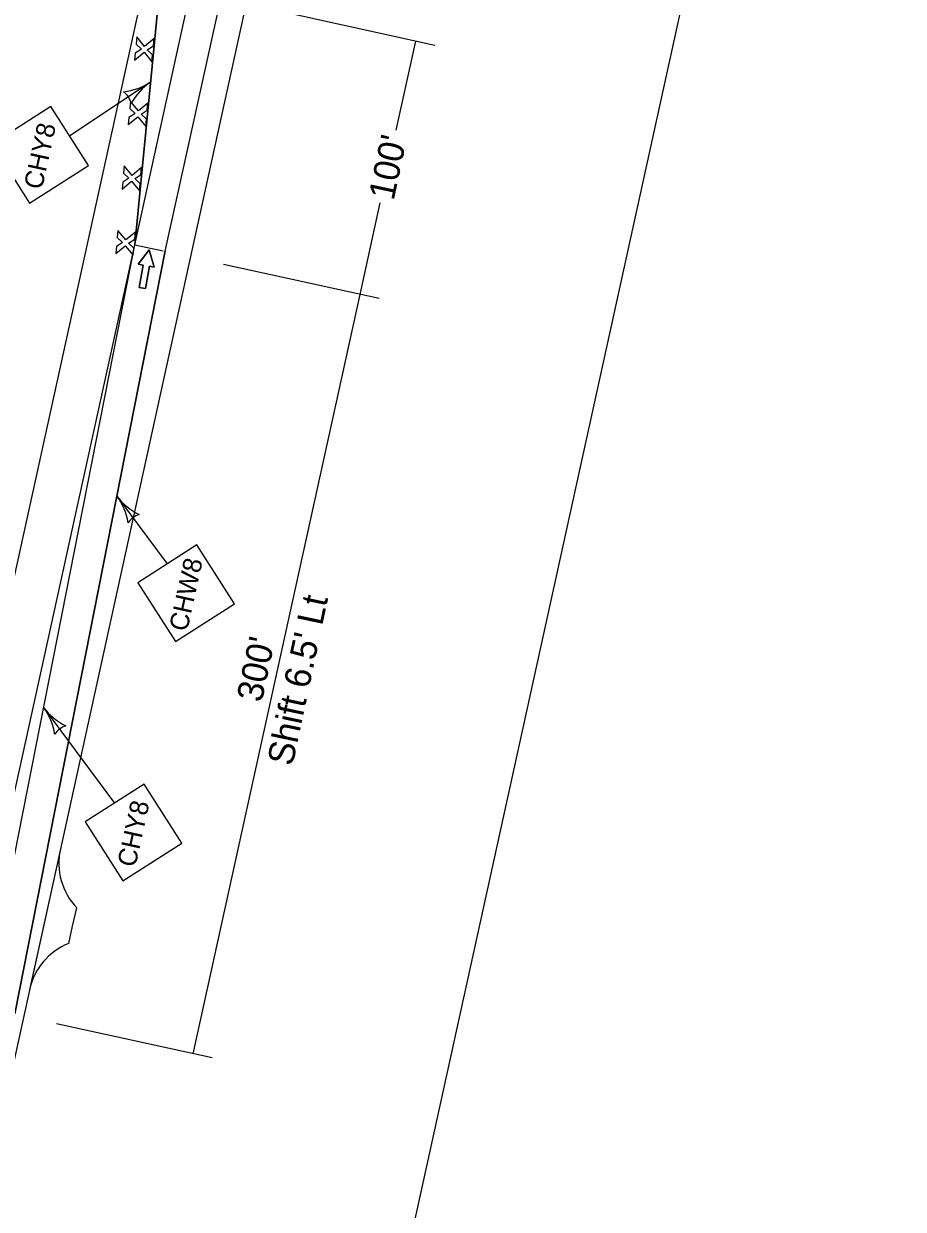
# Model space of a CAD drawing. Extents: x 14104283 to 14120882, y 8635219 to 8671666.
# Drawn here: x 14108147 to 14108486.3, y 8640438 to 8640895.4 of the extents above; entities that cross this region are included whole.
import ezdxf

# ---------------------------------------------------------------- set-up
doc = ezdxf.new("R2010")
doc.units = 0
for name, color, linetype in [('Cell', 7, 'Continuous'), ('dsnNonPlotable', 7, 'Continuous'), ('dsnPaintExistingEdgeLineRightWhite', 7, 'Continuous'), ('dsnPaintPlaceBrokenLineWhite', 7, 'Continuous'), ('dsnPaintRemoveDoubleCenterLineYellow', 7, 'Continuous'), ('dsnShadingGranular', 7, 'Continuous'), ('dsnShadingPaved', 7, 'Continuous'), ('dsnStdLabel', 7, 'Continuous'), ('dsnStgShadingPrevPav', 7, 'Continuous'), ('dsnTapePlaceChannelizingLaneWhite', 7, 'Continuous'), ('dsnTapePlaceChannelizingLaneYellow', 7, 'Continuous')]:
    doc.layers.add(name, color=color, linetype=linetype)

msp = doc.modelspace()

# ---------------------------------------------------------------- linework, layer by layer
at = {"layer": 'Cell'}
for p, q in [((14108190.6, 8640890.31), (14108190.33, 8640887.57)), ((14108190.33, 8640887.57), (14108192.4, 8640885.61)), ((14108193.63, 8640886.62), (14108190.6, 8640890.31)), ((14108197.32, 8640889.66), (14108193.63, 8640886.62)), ((14108194.64, 8640885.39), (14108197.05, 8640886.92)), ((14108197.05, 8640886.92), (14108197.32, 8640889.66)), ((14108189.73, 8640881.35), (14108193.41, 8640884.38)), ((14108189.99, 8640884.09), (14108189.73, 8640881.35)), ((14108192.4, 8640885.61), (14108189.99, 8640884.09)), ((14108193.41, 8640884.38), (14108196.45, 8640880.7)), ((14108196.71, 8640883.43), (14108194.64, 8640885.39)), ((14108196.45, 8640880.7), (14108196.71, 8640883.43)), ((14108188.18, 8640865.42), (14108187.92, 8640862.69)), ((14108191.21, 8640861.74), (14108188.18, 8640865.42)), ((14108194.9, 8640864.77), (14108191.21, 8640861.74)), ((14108194.63, 8640862.04), (14108194.9, 8640864.77)), ((14108187.31, 8640856.47), (14108191, 8640859.5)), ((14108187.58, 8640859.2), (14108187.31, 8640856.47)), ((14108189.99, 8640860.73), (14108187.58, 8640859.2)), ((14108187.92, 8640862.69), (14108189.99, 8640860.73)), ((14108191, 8640859.5), (14108194.03, 8640855.81)), ((14108192.23, 8640860.51), (14108194.63, 8640862.04)), ((14108194.3, 8640858.55), (14108192.23, 8640860.51)), ((14108194.03, 8640855.81), (14108194.3, 8640858.55)), ((14108185.77, 8640840.54), (14108185.5, 8640837.8)), ((14108188.8, 8640836.86), (14108185.77, 8640840.54)), ((14108185.5, 8640837.8), (14108187.57, 8640835.85)), ((14108192.48, 8640839.89), (14108188.8, 8640836.86)), ((14108189.81, 8640835.63), (14108192.22, 8640837.15)), ((14108192.22, 8640837.15), (14108192.48, 8640839.89)), ((14108184.9, 8640831.58), (14108188.58, 8640834.62)), ((14108185.16, 8640834.32), (14108184.9, 8640831.58)), ((14108187.57, 8640835.85), (14108185.16, 8640834.32)), ((14108188.58, 8640834.62), (14108191.61, 8640830.93)), ((14108191.88, 8640833.67), (14108189.81, 8640835.63)), ((14108191.61, 8640830.93), (14108191.88, 8640833.67)), ((14108183.35, 8640815.66), (14108183.08, 8640812.92)), ((14108186.38, 8640811.97), (14108183.35, 8640815.66)), ((14108190.07, 8640815.01), (14108186.38, 8640811.97)), ((14108189.8, 8640812.27), (14108190.07, 8640815.01)), ((14108182.48, 8640806.7), (14108186.16, 8640809.73)), ((14108182.74, 8640809.44), (14108182.48, 8640806.7)), ((14108185.15, 8640810.96), (14108182.74, 8640809.44)), ((14108183.08, 8640812.92), (14108185.15, 8640810.96)), ((14108186.16, 8640809.73), (14108189.2, 8640806.05)), ((14108187.39, 8640810.75), (14108189.8, 8640812.27)), ((14108189.46, 8640808.79), (14108187.39, 8640810.75)), ((14108189.2, 8640806.05), (14108189.46, 8640808.79))]:
    msp.add_line(p, q, dxfattribs=at)
msp.add_lwpolyline([(14108193.92, 8640793.22), (14108191.46, 8640793.67), (14108193.03, 8640802.28), (14108191.19, 8640802.62), (14108195.38, 8640808.21), (14108197.33, 8640801.5), (14108195.49, 8640801.83)], close=True, dxfattribs=at)
msp.add_lwpolyline([(14108195.49, 8640801.83), (14108197.33, 8640801.5), (14108195.38, 8640808.21), (14108191.19, 8640802.62), (14108193.03, 8640802.28), (14108191.46, 8640793.67), (14108193.92, 8640793.22), (14108195.49, 8640801.83)], dxfattribs=at)
at = {"layer": 'dsnNonPlotable'}
msp.add_lwpolyline([(14107651.31, 8639844.94), (14107987.7, 8641375.92), (14108480.93, 8641267.54), (14108144.54, 8639736.56)], close=True, dxfattribs=at)
at = {"layer": 'dsnPaintExistingEdgeLineRightWhite'}
msp.add_line((14108201.57, 8640807.63), (14108723.98, 8643185.75), dxfattribs=at)
at = {"layer": 'dsnPaintPlaceBrokenLineWhite'}
msp.add_line((14108189.82, 8640810.08), (14108306.37, 8641340.66), dxfattribs=at)
at = {"layer": 'dsnPaintRemoveDoubleCenterLineYellow'}
msp.add_line((14108099.08, 8640397.01), (14108306.37, 8641340.66), dxfattribs=at)
at = {"layer": 'dsnShadingGranular'}
for p, q in [((14108161.12, 8640576.89), (14108155.11, 8640549.54)), ((14108155.11, 8640549.54), (14108149.21, 8640522.69))]:
    msp.add_line(p, q, dxfattribs=at)
at = {"layer": 'dsnShadingPaved'}
for p, q in [((14108201.57, 8640807.63), (14108723.98, 8643185.75)), ((14108199.55, 8640910.32), (14108189.82, 8640810.08)), ((14108131.8, 8640515.67), (14108189.82, 8640810.08)), ((14108189.82, 8640810.08), (14108200.83, 8640807.79)), ((14108201.59, 8640807.75), (14108143.57, 8640513.35))]:
    msp.add_line(p, q, dxfattribs=at)
at = {"layer": 'dsnStdLabel'}
for p, q in [((14108305.55, 8640887.04), (14108245.5, 8640900.23)), ((14108290.67, 8640854.29), (14108298.23, 8640888.71)), ((14108195.99, 8640872.93), (14108164.66, 8640852.05)), ((14108276.76, 8640790.98), (14108284.53, 8640826.33)), ((14108284.09, 8640789.37), (14108224.04, 8640802.56)), ((14108212.4, 8640497.96), (14108276.76, 8640790.98)), ((14108182.94, 8640713.12), (14108202.34, 8640687.01)), ((14108154.64, 8640631.59), (14108182.06, 8640594.68)), ((14108219.72, 8640496.35), (14108159.67, 8640509.54))]:
    msp.add_line(p, q, dxfattribs=at)
for points in [[(14108149.19, 8640826.12), (14108171.94, 8640840.67), (14108157.39, 8640863.42), (14108134.64, 8640848.87)], [(14108205.52, 8640656.99), (14108228.26, 8640671.54), (14108213.71, 8640694.28), (14108190.97, 8640679.73)], [(14108185.24, 8640564.66), (14108207.98, 8640579.21), (14108193.43, 8640601.96), (14108170.69, 8640587.41)]]:
    msp.add_lwpolyline(points, close=True, dxfattribs=at)
for centre, radius, start, end in [((14108183.26, 8640892.02), 22.95, 275.6133, 303.6846), ((14108208.72, 8640853.83), 22.95, 123.6844, 151.7557), ((14108179.98, 8640862.25), 8.86, 15.9502, 51.4187), ((14108164.52, 8640699.44), 22.95, 8.5344, 36.6057), ((14108201.36, 8640726.81), 22.95, 216.6055, 244.6768), ((14108194.42, 8640697.68), 8.86, 108.8714, 144.3398), ((14108136.22, 8640617.9), 22.95, 8.5344, 36.6057), ((14108173.07, 8640645.27), 22.95, 216.6055, 244.6768), ((14108166.12, 8640616.14), 8.86, 108.8714, 144.3398)]:
    msp.add_arc(centre, radius, start, end, dxfattribs=at)
at = {"layer": 'dsnStgShadingPrevPav'}
for p, q in [((14108161.12, 8640576.89), (14108155.11, 8640549.54)), ((14108165.86, 8640547.18), (14108167.42, 8640554.3)), ((14108155.11, 8640549.54), (14108149.21, 8640522.69)), ((14108164.4, 8640540.56), (14108165.86, 8640547.18))]:
    msp.add_line(p, q, dxfattribs=at)
msp.add_lwpolyline([(14108081.5, 8640400.87), (14108123.34, 8640591.33), (14108126.55, 8640605.98), (14108216.67, 8641016.2), (14108268.16, 8641250.61), (14108382.95, 8641773.15), (14108422.02, 8641764.57), (14108309.38, 8641251.8), (14108270.22, 8641073.55), (14108265.93, 8641054.01), (14108255.74, 8641007.62), (14108202.1, 8640763.44), (14108120.56, 8640392.29)], close=True, dxfattribs=at)
for centre, start, end in [((14108185.53, 8640571.53), 167.6114, 223.5657), ((14108173.63, 8640517.32), 111.6547, 167.6089)]:
    msp.add_arc(centre, 25, start, end, dxfattribs=at)
at = {"layer": 'dsnTapePlaceChannelizingLaneWhite'}
msp.add_line((14108143.57, 8640513.35), (14108201.59, 8640807.75), dxfattribs=at)
at = {"layer": 'dsnTapePlaceChannelizingLaneYellow'}
for p, q in [((14108189.82, 8640810.08), (14108199.55, 8640910.32)), ((14108131.8, 8640515.67), (14108189.82, 8640810.08))]:
    msp.add_line(p, q, dxfattribs=at)

# ---------------------------------------------------------------- texts
at = {"layer": 'dsnStdLabel'}
for s, height, rotation, p in [('CHY8', 7.2, 77.6078, (14108153.97, 8640831.11)), ("100'", 10, 78.0531, (14108289.69, 8640826.86)), ('CHW8', 7.2, 77.6078, (14108210, 8640660.61)), ("Shift 6.5' Lt", 10, 78.0531, (14108250.63, 8640608.68)), ("300'", 10, 78.0531, (14108238.8, 8640633.24)), ('CHY8', 7.2, 77.6078, (14108190.02, 8640569.65))]:
    msp.add_text(s, height=height, rotation=rotation, dxfattribs=at).set_placement(p)

doc.saveas('drawing.dxf')
